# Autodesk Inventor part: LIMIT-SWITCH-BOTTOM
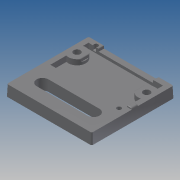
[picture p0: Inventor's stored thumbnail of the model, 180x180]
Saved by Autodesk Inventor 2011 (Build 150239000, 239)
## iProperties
Created: 2007-08
Part Number: LIMIT-SWITCH-BOTTOM
Material: ABS Plastic
Document SubType Name: Modeling
Designer: Tyler
Density: 1.06 g/cm^3
Author: Tyler
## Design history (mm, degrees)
feature "Base1"
workplane "Work Plane1"
body "Solid1"
